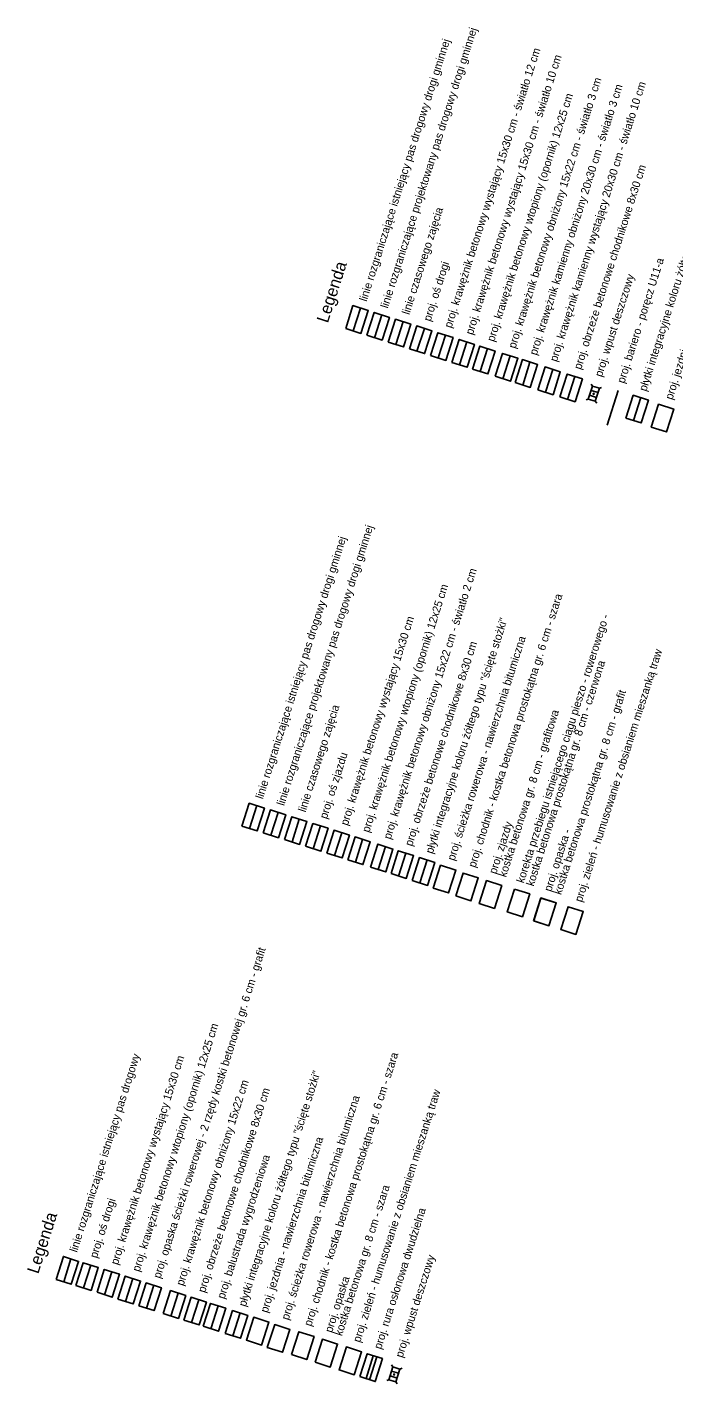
# Model space of a CAD drawing. Extents: x 6526191 to 6550417, y 6005093 to 6049233.
# Drawn here: x 6526771.2 to 6526852.2, y 6049063.2 to 6049232.8 of the extents above; entities that cross this region are included whole.
import ezdxf

# ---------------------------------------------------------------- set-up
doc = ezdxf.new("R2010")
doc.units = 0
for name, color, linetype in [('Default', 7, 'Continuous'), ('DRAFT_balustrady', 7, 'Continuous'), ('DRAFT_kraweznik obnizony', 7, 'Continuous'), ('DRAFT_kraweznik wystajacy', 7, 'Continuous'), ('DRAFT_linie rozgraniczające', 7, 'Continuous'), ('DRAFT_obrzeze', 7, 'Continuous'), ('DRAFT_opis', 7, 'Continuous'), ('DRAFT_opornik betonowy', 7, 'Continuous'), ('DRAFT_oś drogi', 7, 'Continuous'), ('DRAFT_rury osłonowe', 7, 'Continuous'), ('DRAFT_wpust deszczowy', 7, 'Continuous'), ('fill chodnik', 7, 'Continuous'), ('fill jezdnia manewrowa', 7, 'Continuous'), ('fill jezdnia plac', 7, 'Continuous'), ('fill zjazdy', 7, 'Continuous'), ('obrzeze', 7, 'Continuous')]:
    doc.layers.add(name, color=color, linetype=linetype)

msp = doc.modelspace()

# ---------------------------------------------------------------- linework, layer by layer
at = {"layer": 'Default'}
for points in [[(6526811.11, 6049195.15), (6526812.02, 6049198.01), (6526813.93, 6049197.4), (6526813.01, 6049194.54)], [(6526813.77, 6049194.31), (6526814.68, 6049197.16), (6526816.58, 6049196.55), (6526815.67, 6049193.7)], [(6526816.42, 6049193.46), (6526817.34, 6049196.32), (6526819.24, 6049195.71), (6526818.33, 6049192.85)], [(6526819.08, 6049192.61), (6526819.99, 6049195.47), (6526821.9, 6049194.86), (6526820.98, 6049192.01)], [(6526821.74, 6049191.77), (6526822.65, 6049194.63), (6526824.55, 6049194.02), (6526823.64, 6049191.16)], [(6526824.39, 6049190.92), (6526825.31, 6049193.78), (6526827.21, 6049193.17), (6526826.3, 6049190.32)], [(6526826.99, 6049190.09), (6526827.91, 6049192.95), (6526829.81, 6049192.34), (6526828.9, 6049189.48)], [(6526829.83, 6049189.18), (6526830.74, 6049192.04), (6526832.65, 6049191.43), (6526831.73, 6049188.57)], [(6526832.31, 6049188.4), (6526833.22, 6049191.26), (6526835.13, 6049190.65), (6526834.21, 6049187.79)], [(6526835.14, 6049187.49), (6526836.06, 6049190.35), (6526837.96, 6049189.74), (6526837.05, 6049186.88)], [(6526837.92, 6049186.6), (6526838.83, 6049189.46), (6526840.73, 6049188.85), (6526839.82, 6049185.99)], [(6526846.18, 6049183.96), (6526847.09, 6049186.82), (6526848.99, 6049186.21), (6526848.08, 6049183.35)], [(6526798.12, 6049132.96), (6526799.04, 6049135.82), (6526800.94, 6049135.21), (6526800.03, 6049132.35)], [(6526800.78, 6049132.12), (6526801.69, 6049134.97), (6526803.6, 6049134.37), (6526802.69, 6049131.51)], [(6526803.44, 6049131.27), (6526804.35, 6049134.13), (6526806.26, 6049133.52), (6526805.34, 6049130.66)], [(6526806.09, 6049130.43), (6526807.01, 6049133.28), (6526808.91, 6049132.68), (6526808, 6049129.82)], [(6526808.75, 6049129.58), (6526809.66, 6049132.44), (6526811.57, 6049131.83), (6526810.66, 6049128.97)], [(6526811.37, 6049128.75), (6526812.28, 6049131.6), (6526814.19, 6049130.99), (6526813.27, 6049128.14)], [(6526814.2, 6049127.84), (6526815.12, 6049130.7), (6526817.02, 6049130.09), (6526816.11, 6049127.23)], [(6526816.78, 6049127.02), (6526817.69, 6049129.87), (6526819.6, 6049129.27), (6526818.68, 6049126.41)], [(6526819.44, 6049126.16), (6526820.36, 6049129.02), (6526822.26, 6049128.41), (6526821.35, 6049125.55)], [(6526774.86, 6049076.3), (6526775.78, 6049079.16), (6526777.68, 6049078.55), (6526776.77, 6049075.69)], [(6526777.33, 6049075.52), (6526778.25, 6049078.38), (6526780.15, 6049077.77), (6526779.24, 6049074.91)], [(6526779.99, 6049074.68), (6526780.9, 6049077.54), (6526782.81, 6049076.93), (6526781.89, 6049074.07)], [(6526782.61, 6049073.84), (6526783.52, 6049076.7), (6526785.43, 6049076.09), (6526784.51, 6049073.23)], [(6526785.22, 6049073), (6526786.14, 6049075.86), (6526788.04, 6049075.25), (6526787.13, 6049072.4)], [(6526788.28, 6049072.03), (6526789.19, 6049074.89), (6526791.09, 6049074.28), (6526790.18, 6049071.42)], [(6526790.85, 6049071.21), (6526791.76, 6049074.06), (6526793.67, 6049073.46), (6526792.76, 6049070.6)], [(6526793.28, 6049070.43), (6526794.2, 6049073.29), (6526796.1, 6049072.68), (6526795.19, 6049069.82)], [(6526796.04, 6049069.55), (6526796.96, 6049072.4), (6526798.86, 6049071.8), (6526797.95, 6049068.94)], [(6526812.89, 6049064.14), (6526813.81, 6049067), (6526815.71, 6049066.39), (6526814.8, 6049063.53)]]:
    msp.add_lwpolyline(points, close=True, dxfattribs=at)
at = {"layer": 'DRAFT_balustrady'}
msp.add_line((6526794.23, 6049070.12), (6526795.15, 6049072.98), dxfattribs=at)
at = {"layer": 'DRAFT_kraweznik obnizony'}
for p, q in [((6526830.78, 6049188.88), (6526831.69, 6049191.74)), ((6526847.13, 6049183.65), (6526848.04, 6049186.51)), ((6526815.16, 6049127.53), (6526816.07, 6049130.39)), ((6526820.4, 6049125.86), (6526821.31, 6049128.72)), ((6526789.23, 6049071.72), (6526790.14, 6049074.58)), ((6526797, 6049069.24), (6526797.91, 6049072.1))]:
    msp.add_line(p, q, dxfattribs=at)
at = {"layer": 'DRAFT_kraweznik wystajacy'}
for p, q in [((6526822.69, 6049191.47), (6526823.6, 6049194.32)), ((6526825.35, 6049190.62), (6526826.26, 6049193.48)), ((6526836.09, 6049187.19), (6526837.01, 6049190.05)), ((6526809.7, 6049129.28), (6526810.62, 6049132.13)), ((6526780.94, 6049074.37), (6526781.86, 6049077.23))]:
    msp.add_line(p, q, dxfattribs=at)
msp.add_lwpolyline([(6526829.72, 6049122.67), (6526830.64, 6049125.53), (6526828.73, 6049126.14), (6526827.82, 6049123.28), (6526829.72, 6049122.67)], dxfattribs=at)
msp.add_lwpolyline([(6526807.28, 6049065.95), (6526808.19, 6049068.81), (6526810.09, 6049068.2), (6526809.18, 6049065.34)], close=True, dxfattribs=at)
at = {"layer": 'DRAFT_linie rozgraniczające'}
for p, q in [((6526812.06, 6049194.85), (6526812.97, 6049197.7)), ((6526814.72, 6049194), (6526815.63, 6049196.86)), ((6526817.38, 6049193.16), (6526818.29, 6049196.01)), ((6526799.08, 6049132.66), (6526799.99, 6049135.52)), ((6526801.73, 6049131.81), (6526802.65, 6049134.67)), ((6526804.39, 6049130.97), (6526805.3, 6049133.82)), ((6526775.82, 6049076), (6526776.73, 6049078.85))]:
    msp.add_line(p, q, dxfattribs=at)
at = {"layer": 'DRAFT_obrzeze'}
for p, q in [((6526838.87, 6049186.29), (6526839.78, 6049189.15)), ((6526817.73, 6049126.71), (6526818.64, 6049129.57)), ((6526791.8, 6049070.9), (6526792.72, 6049073.76))]:
    msp.add_line(p, q, dxfattribs=at)
for points in [[(6526832.24, 6049125.08), (6526834.15, 6049124.47), (6526833.23, 6049121.62), (6526831.33, 6049122.22)], [(6526838.93, 6049122.88), (6526840.83, 6049122.27), (6526839.92, 6049119.41), (6526838.01, 6049120.02)], [(6526811.19, 6049067.85), (6526813.09, 6049067.24), (6526812.18, 6049064.38), (6526810.27, 6049064.99)]]:
    msp.add_lwpolyline(points, close=True, dxfattribs=at)
at = {"layer": 'DRAFT_opis'}
msp.add_line((6526843.82, 6049183.09), (6526845.2, 6049187.42), dxfattribs=at)
at = {"layer": 'DRAFT_opornik betonowy'}
for p, q in [((6526827.95, 6049189.78), (6526828.86, 6049192.64)), ((6526833.26, 6049188.09), (6526834.17, 6049190.95)), ((6526812.32, 6049128.44), (6526813.23, 6049131.3)), ((6526783.56, 6049073.54), (6526784.47, 6049076.39)), ((6526786.18, 6049072.7), (6526787.09, 6049075.56))]:
    msp.add_line(p, q, dxfattribs=at)
at = {"layer": 'DRAFT_oś drogi'}
for p, q in [((6526820.03, 6049192.31), (6526820.95, 6049195.17)), ((6526807.05, 6049130.12), (6526807.96, 6049132.98)), ((6526778.29, 6049075.22), (6526779.2, 6049078.08))]:
    msp.add_line(p, q, dxfattribs=at)
at = {"layer": 'DRAFT_rury osłonowe'}
for p, q in [((6526813.65, 6049063.9), (6526814.56, 6049066.75)), ((6526814.09, 6049063.76), (6526815, 6049066.61))]:
    msp.add_line(p, q, dxfattribs=at)
at = {"layer": 'DRAFT_wpust deszczowy'}
for p, q in [((6526841.81, 6049188.2), (6526841.98, 6049187.96)), ((6526841.47, 6049186.34), (6526841.19, 6049186.24)), ((6526841.62, 6049186.82), (6526842.5, 6049186.55)), ((6526841.81, 6049187.42), (6526842.69, 6049187.15)), ((6526842.85, 6049187.68), (6526843.13, 6049187.8)), ((6526842.34, 6049186.06), (6526842.52, 6049185.82)), ((6526816.67, 6049064.23), (6526817.54, 6049063.96)), ((6526816.85, 6049065.61), (6526817.02, 6049065.37)), ((6526816.85, 6049064.83), (6526817.73, 6049064.56)), ((6526817.9, 6049065.09), (6526818.17, 6049065.21)), ((6526816.51, 6049063.75), (6526816.24, 6049063.66)), ((6526817.39, 6049063.48), (6526817.56, 6049063.24))]:
    msp.add_line(p, q, dxfattribs=at)
for points in [[(6526841.47, 6049186.34), (6526841.98, 6049187.96), (6526842.85, 6049187.68), (6526842.34, 6049186.06)], [(6526816.51, 6049063.75), (6526817.02, 6049065.37), (6526817.9, 6049065.09), (6526817.39, 6049063.48)]]:
    msp.add_lwpolyline(points, close=True, dxfattribs=at)
for centre in [(6526842.13, 6049186.99), (6526817.17, 6049064.4)]:
    msp.add_circle(centre, 0.0729, dxfattribs=at)
at = {"layer": 'fill chodnik'}
for points in [[(6526827.82, 6049123.28), (6526828.73, 6049126.14), (6526830.64, 6049125.53), (6526829.72, 6049122.67)], [(6526834.63, 6049121.11), (6526835.54, 6049123.96), (6526837.45, 6049123.35), (6526836.53, 6049120.5)], [(6526807.28, 6049065.95), (6526808.19, 6049068.81), (6526810.09, 6049068.2), (6526809.18, 6049065.34)]]:
    msp.add_lwpolyline(points, close=True, dxfattribs=at)
at = {"layer": 'fill jezdnia manewrowa'}
for points in [[(6526850.26, 6049185.69), (6526852.17, 6049185.08), (6526851.25, 6049182.22), (6526849.35, 6049182.83)], [(6526849.35, 6049182.83), (6526850.26, 6049185.69), (6526852.17, 6049185.08), (6526851.25, 6049182.22)], [(6526822.98, 6049128.07), (6526824.89, 6049127.46), (6526823.97, 6049124.6), (6526822.07, 6049125.21)], [(6526822.07, 6049125.21), (6526822.98, 6049128.07), (6526824.89, 6049127.46), (6526823.97, 6049124.6)], [(6526799.6, 6049071.56), (6526801.5, 6049070.95), (6526800.59, 6049068.09), (6526798.68, 6049068.7)], [(6526798.68, 6049068.7), (6526799.6, 6049071.56), (6526801.5, 6049070.95), (6526800.59, 6049068.09)]]:
    msp.add_lwpolyline(points, close=True, dxfattribs=at)
at = {"layer": 'fill jezdnia plac'}
for points in [[(6526838.01, 6049120.02), (6526838.93, 6049122.88), (6526840.83, 6049122.27), (6526839.92, 6049119.41)], [(6526810.27, 6049064.99), (6526811.19, 6049067.85), (6526813.09, 6049067.24), (6526812.18, 6049064.38)]]:
    msp.add_lwpolyline(points, close=True, dxfattribs=at)
at = {"layer": 'fill zjazdy'}
for points in [[(6526824.88, 6049124.22), (6526825.79, 6049127.08), (6526827.69, 6049126.47), (6526826.78, 6049123.61)], [(6526824.88, 6049124.22), (6526825.79, 6049127.08), (6526827.69, 6049126.47), (6526826.78, 6049123.61)], [(6526834.62, 6049121.11), (6526835.53, 6049123.97), (6526837.44, 6049123.36), (6526836.53, 6049120.5)], [(6526802.22, 6049070.64), (6526804.12, 6049070.03), (6526803.21, 6049067.18), (6526801.3, 6049067.79)], [(6526801.3, 6049067.79), (6526802.22, 6049070.64), (6526804.12, 6049070.03), (6526803.21, 6049067.18)], [(6526804.33, 6049066.89), (6526805.25, 6049069.75), (6526807.15, 6049069.14), (6526806.24, 6049066.28)], [(6526804.33, 6049066.89), (6526805.25, 6049069.75), (6526807.15, 6049069.14), (6526806.24, 6049066.28)]]:
    msp.add_lwpolyline(points, close=True, dxfattribs=at)

# ---------------------------------------------------------------- texts
at = {"layer": 'Default'}
for s, p in [('linie rozgraniczające projektowany pas drogowy drogi gminnej', (6526816.38, 6049197.61)), ('linie rozgraniczające istniejący pas drogowy drogi gminnej', (6526813.73, 6049198.46)), ('proj. krawężnik betonowy wystający 15x30 cm - światło 12 cm', (6526824.34, 6049195.14)), ('proj. krawężnik betonowy wystający 15x30 cm - światło 10 cm', (6526827, 6049194.29)), ('proj. krawężnik betonowy obniżony 15x22 cm - światło 3 cm', (6526832.35, 6049192.58)), ('proj. krawężnik kamienny obniżony 20x30 cm - światło 3 cm', (6526835, 6049191.74)), ('proj. krawężnik kamienny wystający 20x30 cm - światło 10 cm', (6526837.54, 6049190.93)), ('proj. krawężnik betonowy wtopiony (opornik) 12x25 cm', (6526829.69, 6049193.43)), ('płytki integracyjne koloru żółtego typu "ścięte stożki" ', (6526848.72, 6049187.23)), ('proj. obrzeże betonowe chodnikowe 8x30 cm', (6526840.56, 6049189.95)), ('linie czasowego zajęcia', (6526819.07, 6049196.81)), ('proj. jezdnia - nawierzchnia bitumiczna', (6526851.99, 6049186.18)), ('proj. oś drogi', (6526821.73, 6049195.97)), ('proj. bariero - poręcz U11-a', (6526845.98, 6049188.22)), ('proj. wpust deszczowy', (6526843.17, 6049189.03)), ('linie rozgraniczające projektowany pas drogowy drogi gminnej', (6526803.4, 6049135.43)), ('linie rozgraniczające istniejący pas drogowy drogi gminnej', (6526800.74, 6049136.27)), ('proj. krawężnik betonowy obniżony 15x22 cm - światło 2 cm', (6526816.73, 6049131.23)), ('proj. krawężnik betonowy wtopiony (opornik) 12x25 cm', (6526814.06, 6049132.08)), ('proj. chodnik - kostka betonowa prostokątna gr. 6 cm - szara', (6526827.34, 6049127.7)), ('proj. krawężnik betonowy wystający 15x30 cm', (6526811.36, 6049132.95)), ('korekta przebiegu istniejącego ciągu pieszo - rowerowego - ', (6526833.39, 6049125.76)), ('płytki integracyjne koloru żółtego typu "ścięte stożki" ', (6526821.99, 6049129.43)), ('proj. obrzeże betonowe chodnikowe 8x30 cm', (6526819.42, 6049130.37)), ('proj. ścieżka rowerowa - nawierzchnia bitumiczna', (6526824.72, 6049128.56)), ('proj. zieleń - humusowanie z obsianiem mieszanką traw', (6526840.66, 6049123.38)), ('kostka betonowa prostokątna gr. 8 cm - czerwona', (6526834.62, 6049125.37)), ('kostka betonowa prostokątna gr. 8 cm - grafit', (6526838.06, 6049124.3)), ('linie czasowego zajęcia', (6526806.08, 6049134.63)), ('kostka betonowa gr. 8 cm - grafitowa', (6526831.17, 6049126.5)), ('proj. oś zjazdu', (6526808.74, 6049133.78)), ('proj. zjazdy', (6526829.94, 6049126.89)), ('proj. opaska - ', (6526836.83, 6049124.69)), ('proj. opaska ścieżki rowerowej - 2 rzędy kostki betonowej gr. 6 cm - grafit', (6526787.92, 6049076.34)), ('proj. krawężnik betonowy wtopiony (opornik) 12x25 cm', (6526785.3, 6049077.18)), ('linie rozgraniczające istniejący pas drogowy', (6526777.48, 6049079.61)), ('proj. krawężnik betonowy wystający 15x30 cm', (6526782.6, 6049078.04)), ('proj. chodnik - kostka betonowa prostokątna gr. 6 cm - szara', (6526806.8, 6049070.36)), ('płytki integracyjne koloru żółtego typu "ścięte stożki" ', (6526798.59, 6049072.82)), ('proj. krawężnik betonowy obniżony 15x22 cm', (6526790.8, 6049075.42)), ('proj. obrzeże betonowe chodnikowe 8x30 cm', (6526793.5, 6049074.56)), ('proj. zieleń - humusowanie z obsianiem mieszanką traw', (6526812.92, 6049068.34)), ('proj. ścieżka rowerowa - nawierzchnia bitumiczna', (6526803.95, 6049071.14)), ('proj. jezdnia - nawierzchnia bitumiczna', (6526801.33, 6049072.05)), ('proj. balustrada wygrodzeniowa', (6526795.93, 6049073.78)), ('kostka betonowa gr. 8 cm - szara', (6526810.63, 6049069.16)), ('proj. oś drogi', (6526779.98, 6049078.88)), ('proj. rura osłonowa dwudzielna', (6526815.54, 6049067.49)), ('proj. wpust deszczowy', (6526818.22, 6049066.44)), ('proj. opaska', (6526809.4, 6049069.56))]:
    msp.add_text(s, height=1, rotation=72.2754, dxfattribs=at).set_placement(p)
at = {"layer": 'obrzeze'}
for p in [(6526808.87, 6049195.76), (6526772.63, 6049076.91)]:
    msp.add_text('Legenda', height=1.512, rotation=72.2754, dxfattribs=at).set_placement(p)

doc.saveas('drawing.dxf')
